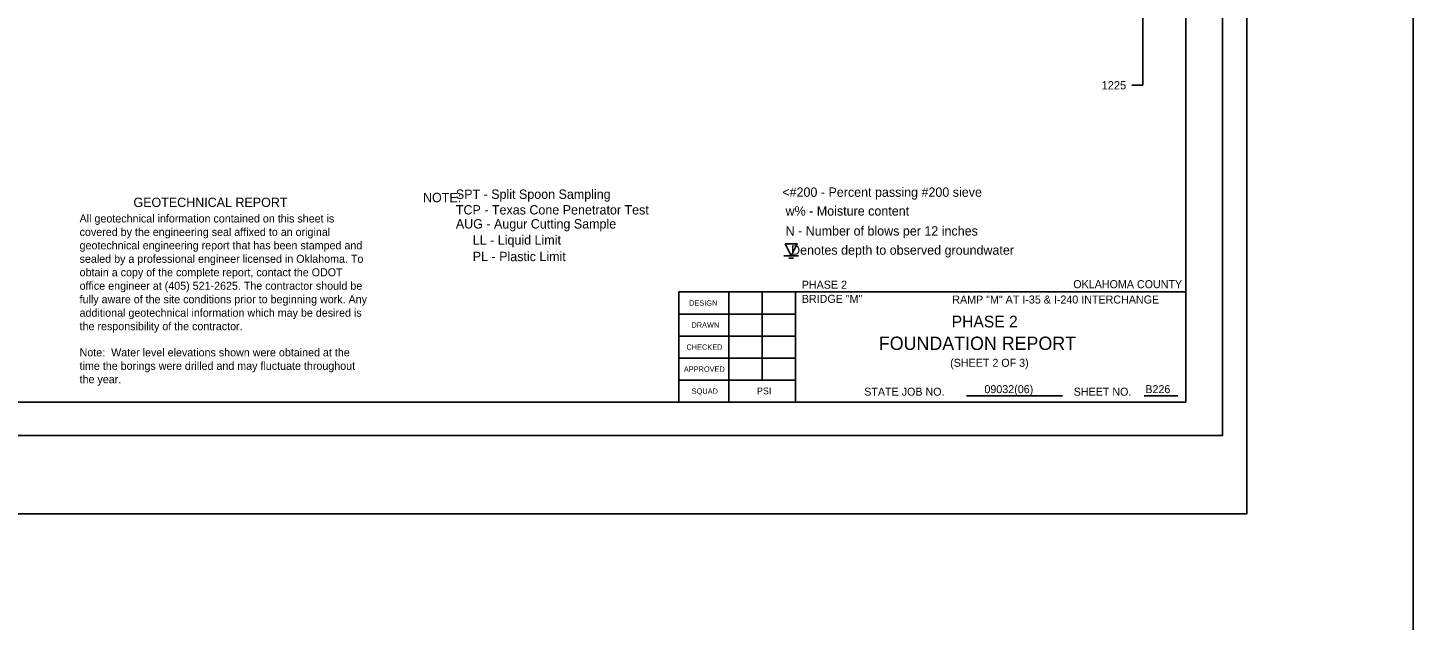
# Model space of a CAD drawing. Extents: x 2150161.5 to 2150203.1, y 143779.5 to 143868.5.
# Drawn here: x 2150182.3 to 2150203.07, y 143808.09 to 143816.97 of the extents above; entities that cross this region are included whole.
import ezdxf

# ---------------------------------------------------------------- set-up
doc = ezdxf.new("R2010")
doc.units = 0
for name, color, linetype in [('Default', 7, 'Continuous'), ('S', 7, 'Continuous'), ('SHT_Plot_Shape_Full', 7, 'Continuous'), ('SHT_Plot_Shape_Half', 7, 'Continuous'), ('SHT_Sheet_Border', 7, 'Continuous'), ('SHT_Standard_Sheet_Lines', 7, 'Continuous'), ('SHT_Standard_Sheet_Txt', 7, 'Continuous'), ('T', 7, 'Continuous'), ('T-Title', 7, 'Continuous'), ('Text', 7, 'Continuous')]:
    doc.layers.add(name, color=color, linetype=linetype)

# ---------------------------------------------------------------- blocks, each defined once
blk = doc.blocks.new('DGRFC_WTLEV1')
at = {"layer": 'Default'}
for points in [[(-0.0127, 0), (0.0127, 0)], [(0, 0), (0.0106, 0.0212), (-0.0106, 0.0212), (0, 0)], [(-0.0042, -0.0042), (0.0042, -0.0042)]]:
    blk.add_lwpolyline(points, dxfattribs=at)

msp = doc.modelspace()

# ---------------------------------------------------------------- linework, layer by layer
at = {"layer": 'Default'}
msp.add_line((2150199.018, 143816.11), (2150199.018, 143829.746), dxfattribs=at)
msp.add_lwpolyline([(2150199.018, 143816.11), (2150198.851, 143816.11)], dxfattribs=at)
at = {"layer": 'S'}
msp.add_lwpolyline([(2150161.53, 143868.477), (2150203.071, 143868.477), (2150203.071, 143779.536), (2150161.53, 143779.536)], close=True, dxfattribs=at)
at = {"layer": 'SHT_Plot_Shape_Full'}
msp.add_lwpolyline([(2150164.575, 143833.688), (2150200.575, 143833.688), (2150200.575, 143809.688), (2150164.575, 143809.688)], close=True, dxfattribs=at)
at = {"layer": 'SHT_Plot_Shape_Half'}
msp.add_lwpolyline([(2150166.212, 143832.863), (2150200.212, 143832.863), (2150200.212, 143810.863), (2150166.212, 143810.863)], close=True, dxfattribs=at)
at = {"layer": 'SHT_Sheet_Border'}
for p, q in [((2150192.062, 143811.363), (2150192.062, 143813.013)), ((2150192.062, 143813.013), (2150199.662, 143813.013)), ((2150193.812, 143811.363), (2150193.812, 143813.014))]:
    msp.add_line(p, q, dxfattribs=at)
msp.add_lwpolyline([(2150199.662, 143811.363), (2150168.162, 143811.363), (2150168.162, 143832.363), (2150199.662, 143832.363)], close=True, dxfattribs=at)
at = {"layer": 'SHT_Standard_Sheet_Lines'}
for p, q in [((2150192.812, 143811.363), (2150192.812, 143813.014)), ((2150193.312, 143811.693), (2150193.312, 143813.014)), ((2150196.373, 143811.459), (2150197.813, 143811.459)), ((2150199.038, 143811.459), (2150199.54, 143811.459))]:
    msp.add_line(p, q, dxfattribs=at)
for points in [[(2150193.812, 143812.683), (2150192.062, 143812.683)], [(2150193.812, 143812.353), (2150192.062, 143812.353)], [(2150193.812, 143812.023), (2150192.062, 143812.023)], [(2150193.812, 143811.693), (2150192.062, 143811.693)]]:
    msp.add_lwpolyline(points, dxfattribs=at)

# ---------------------------------------------------------------- block references
at = {"layer": 'Default', "xscale": 8.503919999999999, "yscale": 8.503919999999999}
msp.add_blockref('DGRFC_WTLEV1', (2150193.745, 143813.553), dxfattribs=at)

# ---------------------------------------------------------------- texts
at = {"layer": 'Default'}
msp.add_text('1225', height=0.124, dxfattribs=at).set_placement((2150198.398, 143816.048))
at = {"layer": 'Defpoints'}
msp.add_text('PHASE 2', height=0.175, dxfattribs=at).set_placement((2150196.152, 143812.482))
at = {"layer": 'SHT_Standard_Sheet_Txt'}
for s, height, p in [('DESIGN', 0.08, (2150192.215, 143812.808)), ('DRAWN', 0.08, (2150192.25, 143812.478)), ('CHECKED', 0.08, (2150192.175, 143812.147)), ('APPROVED', 0.08, (2150192.136, 143811.817)), ('STATE JOB NO.', 0.12, (2150194.84, 143811.459)), ('SHEET NO. ', 0.12, (2150197.98, 143811.459)), ('SQUAD', 0.08, (2150192.254, 143811.487))]:
    msp.add_text(s, height=height, dxfattribs=at).set_placement(p)
at = {"layer": 'T'}
for s, height, p in [('PHASE 2', 0.12, (2150193.904, 143813.062)), ('OKLAHOMA COUNTY', 0.12, (2150197.974, 143813.07)), ('BRIDGE "M"', 0.12, (2150193.904, 143812.85)), ('RAMP "M" AT I-35 & I-240 INTERCHANGE', 0.12, (2150196.16, 143812.84)), ('(SHEET 2 OF 3)', 0.12, (2150196.128, 143811.892)), ('PSI', 0.1, (2150193.232, 143811.481)), ('09032(06)', 0.12, (2150196.642, 143811.497)), ('B226', 0.12, (2150199.054, 143811.497))]:
    msp.add_text(s, height=height, dxfattribs=at).set_placement(p)
at = {"layer": 'T-Title'}
msp.add_text('FOUNDATION REPORT', height=0.2, dxfattribs=at).set_placement((2150195.059, 143812.144))
at = {"layer": 'Text'}
for s, height, p in [('NOTE:', 0.14, (2150188.226, 143814.358)), ('    SPT - Split Spoon Sampling', 0.14, (2150188.51, 143814.408)), (' <#200 - Percent passing #200 sieve', 0.14, (2150193.56, 143814.439)), ('GEOTECHNICAL REPORT', 0.14, (2150183.885, 143814.286)), ('    TCP - Texas Cone Penetrator Test', 0.14, (2150188.51, 143814.174)), ('w% - Moisture content', 0.14, (2150193.661, 143814.157)), ('All geotechnical information contained on this sheet is ', 0.12, (2150183.078, 143814.054)), ('    AUG - Augur Cutting Sample', 0.14, (2150188.51, 143813.964)), ('covered by the engineering seal affixed to an original ', 0.12, (2150183.078, 143813.852)), (' LL - Liquid Limit', 0.14, (2150188.92, 143813.722)), ('N - Number of blows per 12 inches', 0.14, (2150193.661, 143813.858)), ('geotechnical engineering report that has been stamped and ', 0.12, (2150183.078, 143813.652)), ('    Denotes depth to observed groundwater', 0.14, (2150193.536, 143813.571)), ('sealed by a professional engineer licensed in Oklahoma. To ', 0.12, (2150183.078, 143813.45)), (' PL - Plastic Limit', 0.14, (2150188.92, 143813.475)), ('obtain a copy of the complete report, contact the ODOT ', 0.12, (2150183.078, 143813.248)), ('office engineer at (405) 521-2625. The contractor should be ', 0.12, (2150183.078, 143813.046)), ('fully aware of the site conditions prior to beginning work. Any ', 0.12, (2150183.078, 143812.844)), ('additional geotechnical information which may be desired is ', 0.12, (2150183.078, 143812.642)), ('the responsibility of the contractor.', 0.12, (2150183.078, 143812.44)), ('Note:  Water level elevations shown were obtained at the ', 0.12, (2150183.078, 143812.048)), ('time the borings were drilled and may fluctuate throughout ', 0.12, (2150183.078, 143811.846)), ('the year.', 0.12, (2150183.078, 143811.646))]:
    msp.add_text(s, height=height, dxfattribs=at).set_placement(p)

doc.saveas('drawing.dxf')
